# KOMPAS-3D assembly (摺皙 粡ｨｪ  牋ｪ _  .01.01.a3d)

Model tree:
1. Болтовое соединение
2. Болтовое соединение (1)
3. Болтовое соединение (2)  (labels: А.01.01; C:\Program Files (x86)\ASCON\KOMPAS-3D V15\Sys\bo_atr.lat; C:\Program Files (x86)\ASCON\KOMPAS-3D V15\Sys\graphic.lyt)
     Расстояние = 80; Ориентация = 2; Расстояние = 173; Расстояние = 6; Расстояние = 1; Расстояние = 1; Расстояние = 1

Expressions: М10-6H (S16)
Referenced files in C:\Users\s.slezkin\Desktop\Раскатчик арок 2\: Пластина крепления _ А.00.01.m3d, Пластина крепления штанги _ А.00.02.m3d, Опорная втулка вала _ A.00.04.m3d, Штанга №1 _ A.00.03.m3d, Направляющая вала _ A.00.05.m3d, Вал _ A.00.06.m3d, Штанга №2 _ A.00.07.m3d, Вилка ролика _ A.00.08.m3d, Втулка ролика _ A.00.09.m3d, Ролик _ А.00.00.01.m3d, Раскатчик арок _ А.01.01_Спецификация.spw
Referenced files in C:\Program Files (x86)\ASCON\KOMPAS-3D V15\Libs\PartLib\DATA\vault\Methods\Kompas\3D\: PLib_Washer_1_712.m3d, PLib_Bolt_1_900.m3d, PLib_Nut_OST92_900.m3d, PLib_Splint_712.m3d, PLib_Nut_2_900.m3d, PLib_Blind_Nut_type1_900.m3d, PLib_Wing_Screw_DIN_1100.m3d
Referenced files in C:\Program Files (x86)\ASCON\KOMPAS-3D V15\Libs\PartLib\DATA\vault\Methods\Kompas\3D\Fastening_GOST\21331_37\: PLib_Screws_with_bead_GOST_21331_911.m3d
Referenced files: GRAPHIC.TDP
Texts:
  (ф) А.00.01 Пластина крепления
  Пластина крепления штанги
  (+) А.00.02 Пластина крепления штанги (1)
  (+) А.00.02 Пластина крепления штанги (2)
  Опорная втулка вала
  (-) A.00.04 Опорная втулка вала
  АД1 ГОСТ 4784-97
  Шайба 2.8.37 ГОСТ 11371-78
  Крепежное изделие ГОСТ
  (-) Шайба 2.8.37 ГОСТ 11371-78 (1)
  (-) Шайба 2.8.37 ГОСТ 11371-78 (2)
  Болт М8x20 ГОСТ 15591-70
  hole1
  hole2
  (-) Болт М8x20 ГОСТ 15591-70 (1)
  (-) Болт М8x20 ГОСТ 15591-70 (2)
  Штанга №1
  (-) A.00.03 Штанга №1
  (-) A.00.05 Направляющая вала
  (-) Шайба 2.8.37 ГОСТ 11371-78 (3)
  (-) Шайба 2.8.37 ГОСТ 11371-78 (4)
  Болт М8x70 ГОСТ 15591-70
  (-) Болт М8x70 ГОСТ 15591-70
  Гайка М8-6H ГОСТ 5915-70
  bcut1
  hcut1
  cut1
  (-) Гайка М8-6H ГОСТ 5915-70
  (-) Шайба 2.8.37 ГОСТ 11371-78 (5)
  (-) A.00.06 Вал
  Гайка М8-6H ГОСТ 5932-73
  (-) Гайка М8-6H ГОСТ 5932-73
  АМц ГОСТ 4784-97
  Шплинт 1,6x16.4 ГОСТ 397-79
  (-) Шплинт 1,6x16.4 ГОСТ 397-79
  Болт М10x180 ГОСТ 15591-70
  (-) Болт М10x180 ГОСТ 15591-70
  Гайка М10-6H (S16) ГОСТ 11860-85
  foc1
  foc2
  Гайка М10-6H(S16)  ГОСТ 11860-85
  (-) Гайка М10-6H (S16) ГОСТ 11860-85
  Штанга №2
  (-) A.00.07 Штанга №2
  Wing screw DIN 316 - M10 x 20 - A
  Wing screw DIN 316-М10 x 20-A
  (-) Wing screw DIN 316 - M10 x 20 - A
  (-) A.00.08 Вилка ролика
  Шайба 2.10.37 ГОСТ 11371-78
  (-) Шайба 2.10.37 ГОСТ 11371-78
  Винт B3.М10x60 ГОСТ 21331-75
  Isp4
  Isp3
  Isp21335
  (-) Винт B3.М10x60 ГОСТ 21331-75
  (-) A.00.09 Втулка ролика
  Колесо от рохли 70х80
  (-) А.00.00.01 Колесо от рохли 70х80
  (-) Шайба 2.8.37 ГОСТ 11371-78 (6)
  (-) Шайба 2.8.37 ГОСТ 11371-78 (7)
  (-) Болт М8x20 ГОСТ 15591-70 (3)
  (-) Болт М8x20 ГОСТ 15591-70 (4)
  Body Specification ( left align )
  Body Specificaton ( centered )
  ГОСТ 11371-78
  ГОСТ 15591-70
  Edge1
  Edge2
  TKR3D
  ГОСТ 5915-70
  ГОСТ 5932-73
  ГОСТ 397-79
  ГОСТ 11860-85
  DIN 316
  ГОСТ 21331-75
